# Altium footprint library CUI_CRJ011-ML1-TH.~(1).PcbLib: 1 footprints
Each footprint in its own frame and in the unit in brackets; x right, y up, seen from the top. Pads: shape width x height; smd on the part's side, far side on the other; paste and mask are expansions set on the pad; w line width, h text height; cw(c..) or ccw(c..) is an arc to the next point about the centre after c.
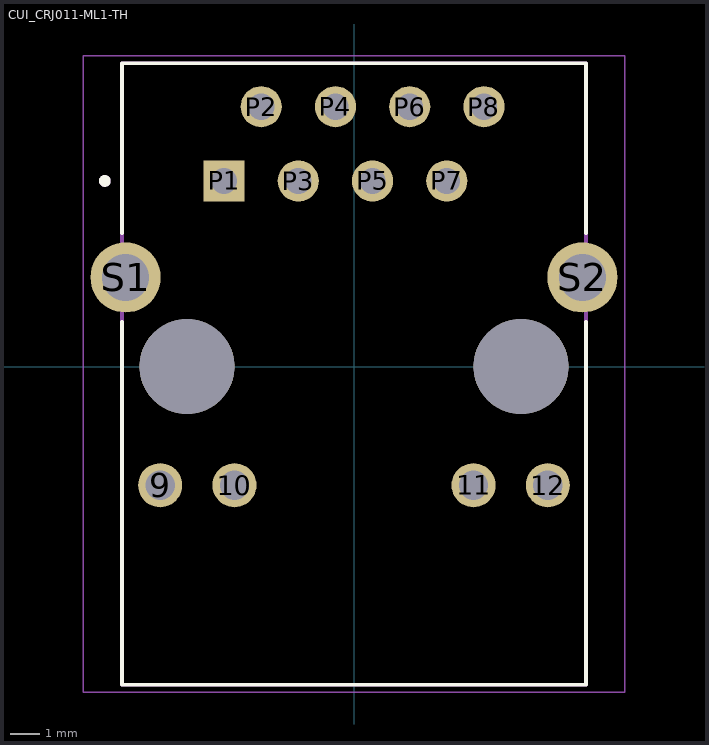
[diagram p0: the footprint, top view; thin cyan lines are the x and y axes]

## CUI_CRJ011-ML1-TH [mm]
height 13.6
pads (16):
  round 1.508 hole 1: 9(-6.63,-4.06) 10(-4.09,-4.06) 11(4.09,-4.06) 12(6.63,-4.06)
  rect 1.408x1.408 / inner round 1.408 / far side rect 1.408x1.408 hole 0.9: P1(-4.445,6.35)
  round 1.408 hole 0.9: P2(-3.175,8.89) P3(-1.905,6.35) P4(-0.635,8.89) P5(0.635,6.35) P6(1.905,8.89) P7(3.175,6.35) P8(4.445,8.89)
  round 2.4 hole 1.6: S1(-7.815,3.05) S2(7.815,3.05)
  round 3.25 hole 3.25 unplated: ""(-5.715,0) ""(5.715,0)
Top Overlay:
  circle w0.2: c-8.525,6.35 r0.1
  lines w0.127: -7.94,1.53 -7.94,-10.89 7.94,-10.89 7.94,1.53 ; -7.94,4.57 -7.94,10.38 7.94,10.38 7.94,4.57
Assembly Top:
  circle w0.2: c-8.525,6.35 r0.1
  lines w0.127: -7.94,-10.89 7.94,-10.89 7.94,10.38 -7.94,10.38 -7.94,-10.89
Courtyard Top:
  lines w0.05: -9.265,-11.14 -9.265,10.63 9.265,10.63 9.265,-11.14 -9.265,-11.14
3D body "step_temp.STEP": height 9.3, standoff -7.75, extent -8.607,-20.92 8.073,0.347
